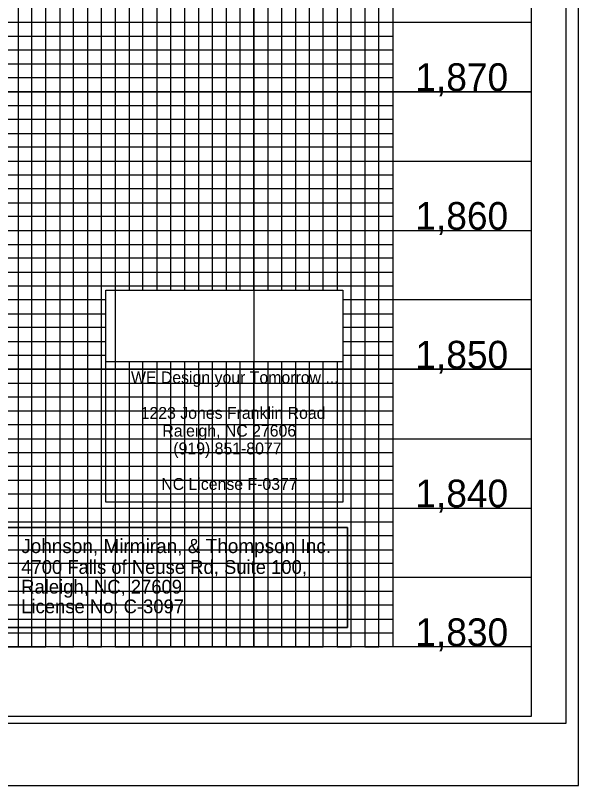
# Model space of a CAD drawing. Extents: x 557032 to 558716, y 525869 to 526969.
# Drawn here: x 558513.5 to 558716.5, y 525869.2 to 526146.7 of the extents above; entities that cross this region are included whole.
import ezdxf

# ---------------------------------------------------------------- set-up
doc = ezdxf.new("R2010")
doc.units = 0
for name, color, linetype in [('Exist Vertical Profile Vertical Axis Label', 7, 'Continuous'), ('Prop DSN Text', 7, 'Continuous'), ('Prop VPI Label', 7, 'Continuous'), ('Sheet Cutting Line CELL', 7, 'Continuous'), ('Sheet DOT Grid CELL', 7, 'Continuous'), ('Sheet Layout Profile Border Port 2', 7, 'Continuous'), ('Sheet Plot Border Inside CELL', 7, 'Continuous'), ('Sheet Plot Border Outside CELL', 7, 'Continuous'), ('Sheet Profile CELL', 7, 'Continuous'), ('Sheet Profile Grid Major CELL', 7, 'Continuous'), ('Sheet Profile Grid Middle CELL', 7, 'Continuous'), ('Sheet Profile Grid Minor CELL', 7, 'Continuous')]:
    doc.layers.add(name, color=color, linetype=linetype)

msp = doc.modelspace()

# ---------------------------------------------------------------- linework, layer by layer
at = {"layer": 'Prop DSN Text'}
for p, q in [((558546.09, 525971.37), (558546.09, 526047.76)), ((558546.09, 526047.76), (558631.43, 526047.76)), ((558631.43, 526047.76), (558631.43, 525971.37)), ((558546.09, 526021.97), (558631.43, 526021.97)), ((558631.43, 525971.37), (558546.09, 525971.37))]:
    msp.add_line(p, q, dxfattribs=at)
at = {"layer": 'Prop VPI Label'}
for points in [[(558546.09, 526021.97), (558631.43, 526021.97), (558631.43, 525971.37), (558546.09, 525971.37)], [(558433.19, 525962.24), (558633.22, 525962.24), (558633.22, 525926.14), (558433.19, 525926.14)], [(558433.19, 525926.14), (558633.22, 525926.14), (558633.22, 525962.24), (558433.19, 525962.24)]]:
    msp.add_lwpolyline(points, close=True, dxfattribs=at)
at = {"layer": 'Sheet Cutting Line CELL'}
msp.add_line((557032.45, 525869.22), (558716.45, 525869.22), dxfattribs=at)
at = {"layer": 'Sheet DOT Grid CELL'}
for p, q in [((558549.45, 526419.22), (558549.45, 525919.22)), ((558599.45, 526419.22), (558599.45, 525919.22)), ((558649.45, 526419.22), (558649.45, 525919.22)), ((557199.45, 526119.22), (558699.34, 526119.22)), ((557199.45, 526069.22), (558699.34, 526069.22)), ((557199.45, 526019.22), (558699.34, 526019.22)), ((557199.45, 525969.22), (558699.34, 525969.22))]:
    msp.add_line(p, q, dxfattribs=at)
at = {"layer": 'Sheet Layout Profile Border Port 2'}
msp.add_lwpolyline([(557249.45, 526419.22), (558649.45, 526419.22), (558649.45, 525919.22), (557249.45, 525919.22)], close=True, dxfattribs=at)
at = {"layer": 'Sheet Plot Border Inside CELL'}
msp.add_lwpolyline([(557045.45, 525891.67), (558711.95, 525891.67), (558711.95, 526946.77), (557045.45, 526946.77)], close=True, dxfattribs=at)
at = {"layer": 'Sheet Plot Border Outside CELL'}
msp.add_lwpolyline([(557032.45, 525869.22), (558716.45, 525869.22), (558716.45, 526969.22), (557032.45, 526969.22)], close=True, dxfattribs=at)
at = {"layer": 'Sheet Profile CELL'}
for p, q in [((558699.45, 525919.22), (557199.45, 525919.22)), ((557199.45, 525894.22), (558699.45, 525894.22))]:
    msp.add_line(p, q, dxfattribs=at)
msp.add_lwpolyline([(558699.45, 526944.22), (557199.45, 526944.22), (557199.45, 525894.22), (558699.45, 525894.22)], close=True, dxfattribs=at)
at = {"layer": 'Sheet Profile Grid Major CELL'}
msp.add_line((558599.45, 525919.22), (558599.45, 525919.22), dxfattribs=at)
for points in [[(558349.45, 525919.22), (558399.45, 525919.22), (558399.45, 526419.22), (558449.45, 526419.22), (558449.45, 525919.22), (558499.45, 525919.22), (558499.45, 526419.22), (558549.45, 526419.22), (558549.45, 526047.76)], [(558599.45, 526047.76), (558599.45, 526419.22), (558649.45, 526419.22), (558649.45, 525919.22)], [(558699.45, 526119.22), (557199.45, 526119.22), (557199.45, 526069.22), (558699.45, 526069.22)], [(558549.45, 526021.97), (558549.45, 525919.22), (558599.45, 525919.22), (558599.45, 525919.22), (558599.45, 526021.97)], [(558699.45, 526019.22), (557199.45, 526019.22), (557199.45, 526019.22), (557199.45, 525969.22), (558699.45, 525969.22)], [(558699.45, 525919.22), (557199.45, 525919.22)]]:
    msp.add_lwpolyline(points, dxfattribs=at)
at = {"layer": 'Sheet Profile Grid Middle CELL'}
for points in [[(558324.45, 526419.22), (558374.45, 526419.22), (558374.45, 525919.22), (558424.45, 525919.22), (558424.45, 526419.22), (558474.45, 526419.22), (558474.45, 525919.22), (558524.45, 525919.22), (558524.45, 526419.22), (558574.45, 526419.22), (558574.45, 526047.76)], [(558624.45, 526047.76), (558624.45, 526419.22)], [(558699.45, 526144.22), (557199.45, 526144.22), (557199.45, 526094.22), (558699.45, 526094.22)], [(558546.09, 526044.22), (557199.45, 526044.22), (557199.45, 525994.22), (558699.45, 525994.22)], [(558699.45, 526044.22), (558631.43, 526044.22)], [(558574.45, 526021.97), (558574.45, 525919.22), (558624.45, 525919.22), (558624.45, 526021.97)], [(558699.45, 525944.22), (557199.45, 525944.22)]]:
    msp.add_lwpolyline(points, dxfattribs=at)
at = {"layer": 'Sheet Profile Grid Minor CELL'}
for p, q in [((557249.45, 526139.22), (558649.45, 526139.22)), ((558649.45, 526134.22), (557249.45, 526134.22)), ((557249.45, 526129.22), (558649.45, 526129.22)), ((558649.45, 526124.22), (557249.45, 526124.22)), ((557249.45, 526114.22), (558649.45, 526114.22)), ((558649.45, 526109.22), (557249.45, 526109.22)), ((557249.45, 526104.22), (558649.45, 526104.22)), ((558649.45, 526099.22), (557249.45, 526099.22)), ((557249.45, 526089.22), (558649.45, 526089.22)), ((558649.45, 526084.22), (557249.45, 526084.22)), ((557249.45, 526079.22), (558649.45, 526079.22)), ((558649.45, 526074.22), (557249.45, 526074.22)), ((557249.45, 526064.22), (558649.45, 526064.22)), ((558649.45, 526059.22), (557249.45, 526059.22)), ((557249.45, 526054.22), (558649.45, 526054.22)), ((558649.45, 526049.22), (557249.45, 526049.22)), ((557249.45, 526039.22), (558546.09, 526039.22)), ((558631.43, 526039.22), (558649.45, 526039.22)), ((558546.09, 526034.22), (557249.45, 526034.22)), ((558649.45, 526034.22), (558631.43, 526034.22)), ((557249.45, 526029.22), (558546.09, 526029.22)), ((558631.43, 526029.22), (558649.45, 526029.22)), ((558546.09, 526024.22), (557249.45, 526024.22)), ((558649.45, 526024.22), (558631.43, 526024.22)), ((557249.45, 526014.22), (558649.45, 526014.22)), ((558649.45, 526009.22), (557249.45, 526009.22)), ((557249.45, 526004.22), (558649.45, 526004.22)), ((558649.45, 525999.22), (557249.45, 525999.22)), ((557249.45, 525989.22), (558649.45, 525989.22)), ((558649.45, 525984.22), (557249.45, 525984.22)), ((557249.45, 525979.22), (558649.45, 525979.22)), ((558649.45, 525974.22), (557249.45, 525974.22)), ((557249.45, 525964.22), (558649.45, 525964.22)), ((558649.45, 525959.22), (557249.45, 525959.22)), ((557249.45, 525954.22), (558649.45, 525954.22)), ((558649.45, 525949.22), (557249.45, 525949.22)), ((557249.45, 525939.22), (558649.45, 525939.22)), ((558649.45, 525934.22), (557249.45, 525934.22)), ((557249.45, 525929.22), (558649.45, 525929.22)), ((557249.45, 525924.22), (558649.45, 525924.22)), ((558649.45, 525924.22), (558649.45, 525924.22))]:
    msp.add_line(p, q, dxfattribs=at)
for points in [[(558514.45, 526419.22), (558514.45, 525919.22), (558519.45, 525919.22), (558519.45, 526419.22)], [(558529.45, 526419.22), (558529.45, 525919.22), (558534.45, 525919.22), (558534.45, 526419.22)], [(558539.45, 526419.22), (558539.45, 525919.22), (558544.45, 525919.22), (558544.45, 526419.22)], [(558554.45, 526419.22), (558554.45, 526047.76)], [(558559.45, 526047.76), (558559.45, 526419.22), (558564.45, 526419.22), (558564.45, 526047.76)], [(558569.45, 526047.76), (558569.45, 526419.22), (558579.45, 526419.22), (558579.45, 526047.76)], [(558584.45, 526047.76), (558584.45, 526419.22), (558589.45, 526419.22), (558589.45, 526047.76)], [(558594.45, 526047.76), (558594.45, 526419.22), (558604.45, 526419.22), (558604.45, 526047.76)], [(558609.45, 526047.76), (558609.45, 526419.22), (558614.45, 526419.22), (558614.45, 526047.76)], [(558619.45, 526047.76), (558619.45, 526419.22), (558629.45, 526419.22), (558629.45, 526047.76)], [(558629.45, 526021.97), (558629.45, 525919.22), (558634.45, 525919.22), (558634.45, 526419.22), (558639.45, 526419.22), (558639.45, 525919.22), (558644.45, 525919.22), (558644.45, 526419.22), (558649.45, 526419.22)], [(558554.45, 526021.97), (558554.45, 525919.22), (558559.45, 525919.22), (558559.45, 526021.97)], [(558564.45, 526021.97), (558564.45, 525919.22), (558569.45, 525919.22), (558569.45, 526021.97)], [(558579.45, 526021.97), (558579.45, 525919.22), (558584.45, 525919.22), (558584.45, 526021.97)], [(558589.45, 526021.97), (558589.45, 525919.22), (558594.45, 525919.22), (558594.45, 526021.97)], [(558604.45, 526021.97), (558604.45, 525919.22), (558609.45, 525919.22), (558609.45, 526021.97)], [(558614.45, 526021.97), (558614.45, 525919.22), (558619.45, 525919.22), (558619.45, 526021.97)]]:
    msp.add_lwpolyline(points, dxfattribs=at)

# ---------------------------------------------------------------- texts
at = {"layer": 'Exist Vertical Profile Vertical Axis Label'}
for s, p in [('1,870', (558657.61, 526119.47)), ('1,870', (558657.61, 526119.47)), ('1,860', (558657.61, 526069.47)), ('1,860', (558657.61, 526069.47)), ('1,850', (558657.61, 526019.47)), ('1,850', (558657.61, 526019.47)), ('1,840', (558657.61, 525969.47)), ('1,840', (558657.61, 525969.47)), ('1,830', (558657.61, 525919.47)), ('1,830', (558657.61, 525919.47))]:
    msp.add_text(s, height=10, dxfattribs=at).set_placement(p)
at = {"layer": 'Prop DSN Text'}
for s, p in [('WE Design your Tomorrow ...', (558555.13, 526014.16)), ('1223 Jones Franklin Road', (558558.62, 526001.36)), ('Raleigh, NC 27606', (558566.44, 525994.96)), ('(919) 851-8077', (558570.38, 525988.56)), ('NC License F-0377', (558566.04, 525975.76))]:
    msp.add_text(s, height=4.2667, rotation=0, dxfattribs=at).set_placement(p)
at = {"layer": 'Prop VPI Label'}
for s, height, p in [('Johnson, Mirmiran, & Thompson Inc.', 5.1112, (558515.57, 525953)), ('4700 Falls of Neuse Rd, Suite 100, ', 4.9652, (558515.57, 525945.49)), ('Raleigh, NC, 27609', 4.9652, (558515.57, 525938.4)), ('License No: C-3097', 4.9652, (558515.57, 525931.31))]:
    msp.add_text(s, height=height, dxfattribs=at).set_placement(p)

doc.saveas('drawing.dxf')
